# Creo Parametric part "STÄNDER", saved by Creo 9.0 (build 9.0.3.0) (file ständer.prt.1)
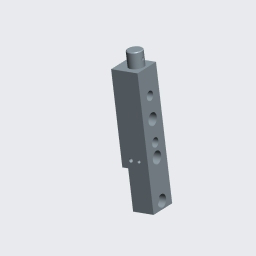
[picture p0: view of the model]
Units: millimeter Kilogram Sec (mmKs); MM, KILOGRAM, SECS
Materials in the file: STAHL

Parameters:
  SCHRAUBEN_GROESSE = "M4x.7"
  METRISCH = "JA"
  WERKSTOFF = "Stahl"
  ERSTELLER = "ARINDA"
  BENENNUNG = "XXX"
  TEILETYP = "K"
  PTC_MASTER_MATERIAL = "STAHL"

Other parameters: ANSENKDURCHMESSER, ANSENKTIEFE, BOHR_DURCHM, MASSE, STEIGUNG, GEWINDEDURCHMESSER, GEWINDEGÄNGE_PRO_INCH

Created from: ARINDA_STARTTEIL.PRT

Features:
  1. coordinate system
  2. datum plane "RECHTS_Y-Z"
  3. datum plane "OBEN_X-Z"
  4. datum plane "VORNE_X-Y"
  5. datum axis
  6. datum axis
  7. datum axis
  8. datum point "PNT0"
  9. extrusion "Profil 1"
  10. extruded cut "Profil 1"
  11. hole "Bohrung 1"
  12. hole "Bohrung 2"
  13. sketch "Skizze 1"
  14. pattern "Muster 1"
  15. hole "Bohrung 3"
  16. hole "Bohrung 3 [12]"
  17. hole "Bohrung 4"
  18. hole "Bohrung 5"
  19. hole "Bohrung 6"
  20. extrusion "Profil 2"
  21. hole "Bohrung 7"
  22. chamfer "Fase 1"

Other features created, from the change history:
  coordinate system "CS1"

Other named items: SÄULE, ANSCHLAG_BODENPLATTE, BOHRUNG_BODENPLATTE, BOHRUNG_FÜHRUNGSLEISTE, STIFTBOHRUNGEN, STIFTBOHRUNG_FÜHRUNGSLEISTE, KURBELBOHRUNG, SICHERUNG_KURBEL, GETRIEBEGEHÄUSEZAPFEN, ZENTRIERUNG_GETRIEBEGEHÄUSE, F0_5, A_X, A_Y, A_Z, CS0

Layers: 01_ACHSEN, 01_ACHSEN_STD, 01_EBENEN_STD, 01_KOORDSYS_STD, 01_KURVEN, 01_PUNKTE_STD, GEWINDE, SAMMELFLÄCHEN, VOLUMENGEOMETRIE

Notes: M4x.7 | LÖSCHEN |  BOHREN (  | 4.500 | DURCH |   -(  |  ) BOHRUNG | M3x.5 | GEWINDEBOHREN | DURCH |  BOHREN (  | 2.500 | DURCH |   -(  |  ) BOHRUNG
